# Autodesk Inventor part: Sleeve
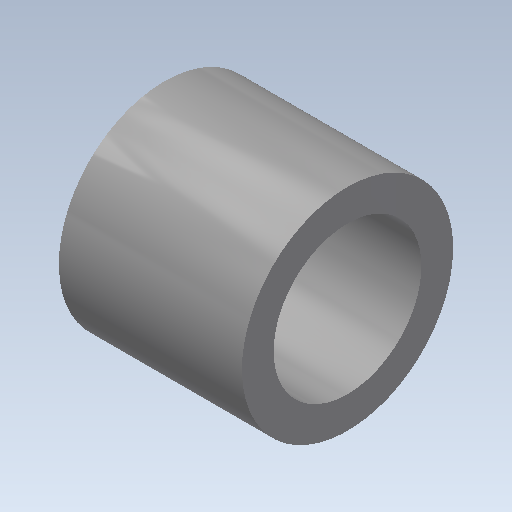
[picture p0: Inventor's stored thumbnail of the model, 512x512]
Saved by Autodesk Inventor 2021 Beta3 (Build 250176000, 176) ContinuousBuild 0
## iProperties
Created: 2012-08
Part Number: Sleeve
Material: Steel
Document SubType Name: Modeling
Designer: John
Mass: 4.06931 g
Surface Area: 7.09365 cm^2
Volume: 0.518383 cm^3
Density: 7.85 g/cm^3
Appearance: Steel
Author: John
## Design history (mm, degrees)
sketch "Sketch1"
  geometry: C1 r 5.715 at (0, 0); C2 r 4.001 at (0, 0); 1 further point
  constraints: 2 centre point, 2 coincident
  dimensions: "d0" = 11.43 diameter of C1; "d2" = 8.001 diameter of C2
extrude "Extrusion1" new body sketch "Sketch1" distance "d3" = 9.906; taper "d4" = 0 deg
body "Solid1"
